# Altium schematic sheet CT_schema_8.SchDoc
size 274 x 160 mm
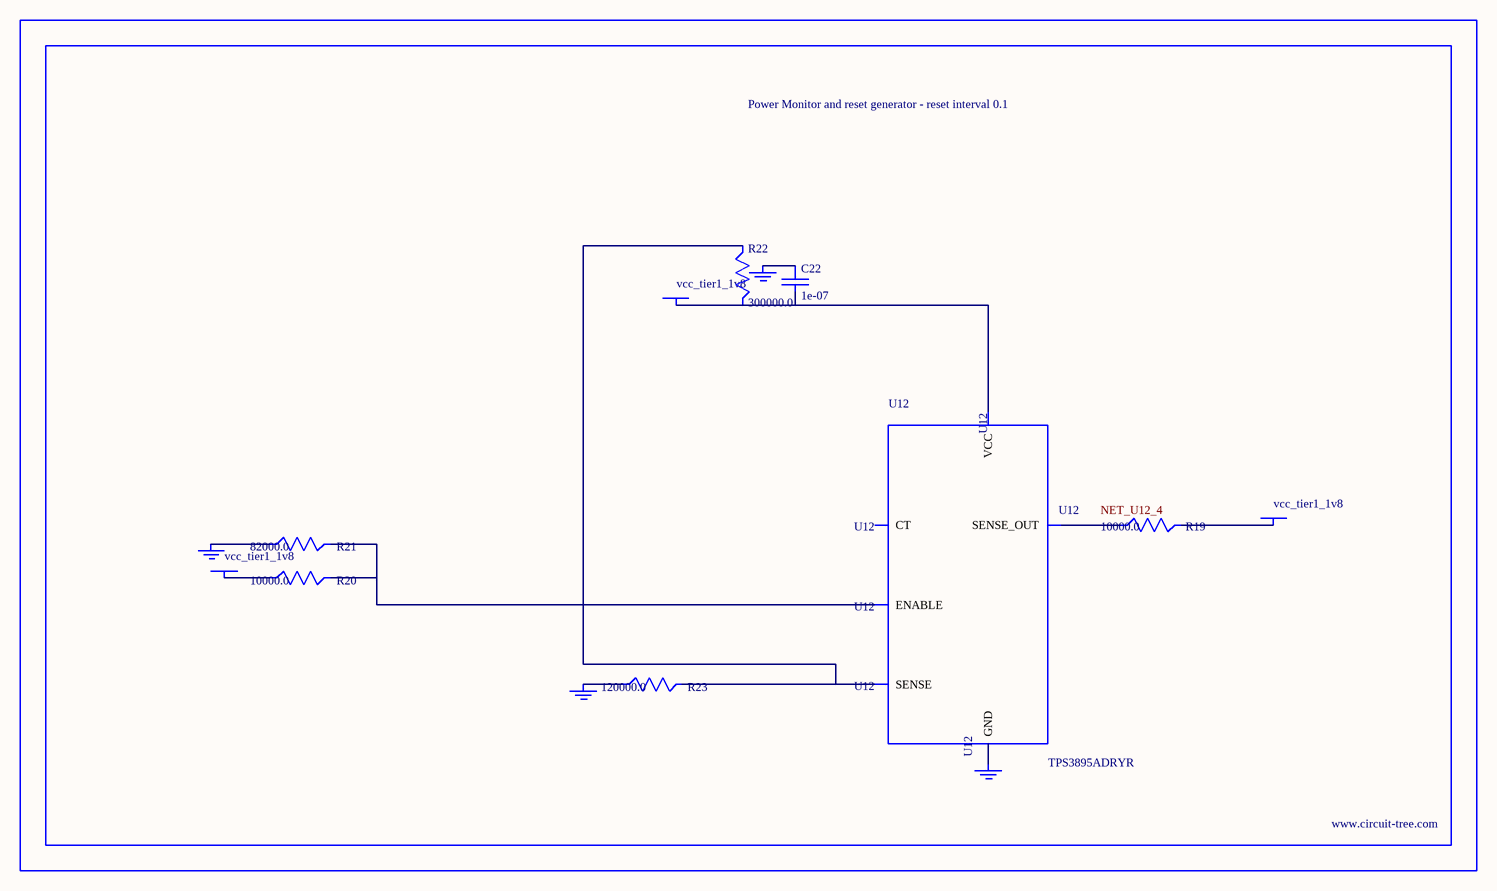
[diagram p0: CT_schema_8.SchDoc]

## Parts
BORDER7  (no value)
C22  1e-07  [C0402]
GND_INSTANCE_7_0  (no value)
GND_INSTANCE_7_1  (no value)
GND_INSTANCE_7_2  (no value)
GND_INSTANCE_7_3  (no value)
POWER_INSTANCE_7_0  vcc_tier1_1v8
POWER_INSTANCE_7_1  vcc_tier1_1v8
POWER_INSTANCE_7_2  vcc_tier1_1v8
R19  10000.0  [R0603]
R20  10000.0  [R0603]
R21  82000.0  [R0603]
R22  300000.0  [R0603]
R23  120000.0  [R0603]
U12  TPS3895ADRYR  [SON-6]

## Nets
NetC22_1: C22.1 GND_INSTANCE_7_2.0(GND)
NetC22_2: C22.2 POWER_INSTANCE_7_2.0(PWR) R22.2 U12.6(VCC)
NetGND_INSTANCE_7_0_0: GND_INSTANCE_7_0.0(GND) R21.1
NetGND_INSTANCE_7_1_0: GND_INSTANCE_7_1.0(GND) R23.1
NetGND_INSTANCE_7_3_0: GND_INSTANCE_7_3.0(GND) U12.2(GND)
NetPOWER_INSTANCE_7_0_0: POWER_INSTANCE_7_0.0(PWR) R20.1
NetPOWER_INSTANCE_7_1_0: POWER_INSTANCE_7_1.0(PWR) R19.2
NetR19_1: R19.1 U12.4(SENSE_OUT)
NetR20_2: R20.2 R21.2 U12.1(ENABLE)
NetR22_1: R22.1 R23.2 U12.3(SENSE)

Not connected (* = marked no-connect by the designer): U12 5(CT)

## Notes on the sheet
- Labels drawn without touching a wire or pin: NET_U12_4

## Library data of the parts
BORDER7 = BORDER_PAGE7
C22 = C0402C104K3RACTU
GND_INSTANCE_7_0-GND_INSTANCE_7_3 = GND
POWER_INSTANCE_7_0-POWER_INSTANCE_7_2 = PWR
R19 R20 = RC0603JR-0710KL
R21 = RC0603JR-0782KL
R22 = RC0603JR-07300KL
R23 = RC0603JR-07120KL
